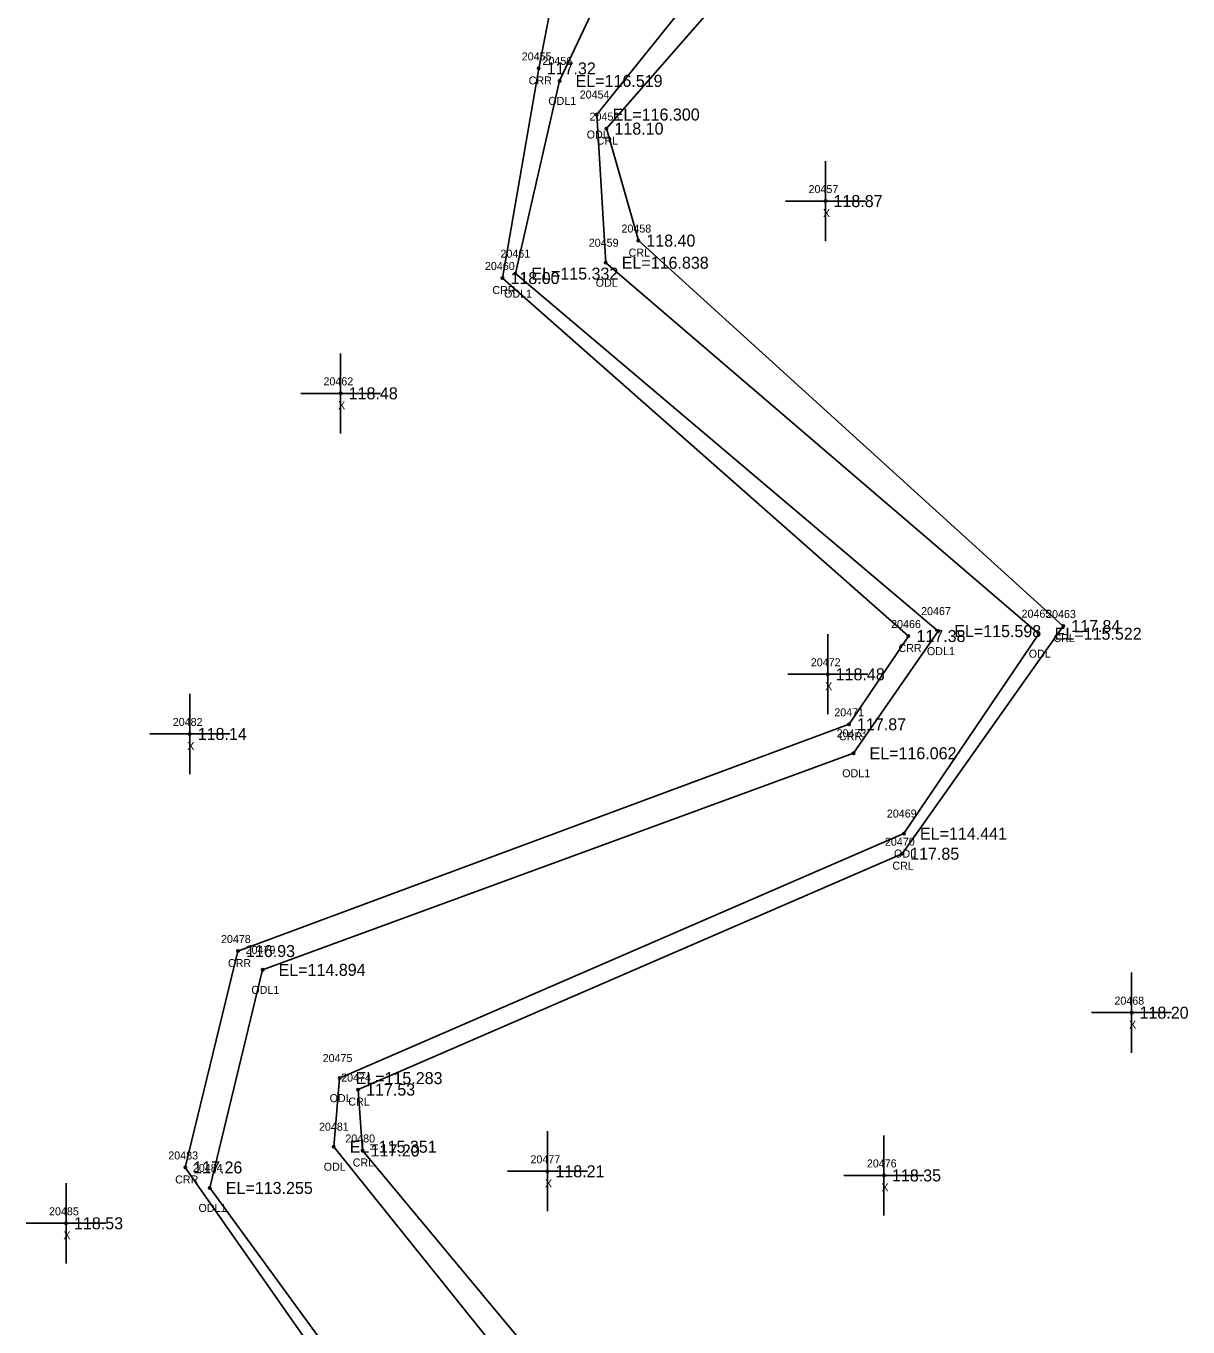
# Model space of a CAD drawing. Extents: x 2375812 to 2377225, y 1024470 to 1025135.
# Drawn here: x 2376487.2 to 2376632.4, y 1024633 to 1024795.6 of the extents above; entities that cross this region are included whole.
import ezdxf

# ---------------------------------------------------------------- set-up
doc = ezdxf.new("R2010")
doc.units = 0
for name, color, linetype in [('RD_EX_H2O', 7, 'Continuous'), ('RD_EX_H2O_txCode', 7, 'Continuous'), ('RD_EX_Misc', 7, 'Continuous'), ('RD_EX_Misc_txCode', 7, 'Continuous'), ('RD_EX_TX_H2O_ELEV', 7, 'Continuous'), ('RD_EX_TX_Misc_ELEV', 7, 'Continuous'), ('RD_SMD_Locator', 7, 'Continuous')]:
    doc.layers.add(name, color=color, linetype=linetype)

msp = doc.modelspace()

# ---------------------------------------------------------------- linework, layer by layer
at = {"layer": 'RD_EX_H2O'}
for points in [[(2376521.35, 1025122.45), (2376536.92, 1025091.14), (2376540.63, 1025083.08), (2376543.66, 1025055.12), (2376543.73, 1025030.97), (2376527.94, 1024982.48), (2376525.52, 1024962.71), (2376529, 1024940.86), (2376531.15, 1024912.48), (2376521.82, 1024868), (2376529.09, 1024848.8), (2376562.19, 1024842.5), (2376569.47, 1024830.15), (2376574.05, 1024803.85), (2376558.51, 1024784.52), (2376559.64, 1024766), (2376613.77, 1024719.65), (2376596.93, 1024694.68), (2376526.36, 1024664.12), (2376525.63, 1024655.55), (2376574.03, 1024595.3), (2376579.09, 1024545.56), (2376560.1, 1024512.81), (2376580.22, 1024476.29)], [(2376510.41, 1025118.87), (2376524.18, 1025090.35), (2376517.39, 1025079.83), (2376512.07, 1025056.47), (2376513.2, 1025032.16), (2376507.89, 1024984.65), (2376510.96, 1024957.77), (2376506.15, 1024940.79), (2376503.27, 1024912.21), (2376508.8, 1024872.61), (2376520.24, 1024833.34), (2376559.55, 1024828.46), (2376560.55, 1024802.93), (2376553.87, 1024788.72), (2376548.34, 1024764.64), (2376601.21, 1024719.97), (2376590.62, 1024704.71), (2376516.74, 1024677.65), (2376510.14, 1024650.4), (2376567.6, 1024571.64), (2376569.87, 1024553.24), (2376548.12, 1024513.5), (2376565.22, 1024475.98)], [(2376554.79, 1024808.22), (2376551.26, 1024790.28), (2376546.73, 1024764.09), (2376597.49, 1024719.36), (2376590.06, 1024708.33), (2376513.66, 1024680), (2376507.07, 1024652.96), (2376563.64, 1024572.19), (2376565.26, 1024557.08), (2376545.13, 1024513.67), (2376559.22, 1024475.85)], [(2376577.78, 1024803.44), (2376559.73, 1024782.76), (2376563.72, 1024768.77), (2376616.84, 1024720.6), (2376596.7, 1024692.16), (2376528.68, 1024662.69), (2376529.24, 1024655.08), (2376574.47, 1024600.74), (2376581.85, 1024543.26), (2376561.1, 1024512.75), (2376586.22, 1024476.41)]]:
    msp.add_lwpolyline(points, dxfattribs=at)
at = {"layer": 'RD_EX_Misc'}
for p, q in [((2376587.12, 1024768.7), (2376587.12, 1024778.7)), ((2376582.12, 1024773.7), (2376592.12, 1024773.7)), ((2376526.5, 1024744.68), (2376526.5, 1024754.68)), ((2376521.5, 1024749.68), (2376531.5, 1024749.68)), ((2376587.39, 1024709.58), (2376587.39, 1024719.58)), ((2376582.39, 1024714.58), (2376592.39, 1024714.58)), ((2376507.63, 1024702.12), (2376507.63, 1024712.12)), ((2376502.63, 1024707.12), (2376512.63, 1024707.12)), ((2376625.38, 1024667.3), (2376625.38, 1024677.3)), ((2376620.38, 1024672.3), (2376630.38, 1024672.3)), ((2376552.35, 1024647.48), (2376552.35, 1024657.48)), ((2376594.43, 1024646.96), (2376594.43, 1024656.96)), ((2376547.35, 1024652.48), (2376557.35, 1024652.48)), ((2376492.16, 1024640.98), (2376492.16, 1024650.98)), ((2376589.43, 1024651.96), (2376599.43, 1024651.96)), ((2376487.16, 1024645.98), (2376497.16, 1024645.98))]:
    msp.add_line(p, q, dxfattribs=at)
at = {"layer": 'RD_SMD_Locator'}
for centre in [(2376551.26, 1024790.28), (2376553.87, 1024788.72), (2376558.51, 1024784.52), (2376559.73, 1024782.76), (2376587.12, 1024773.7), (2376563.72, 1024768.77), (2376559.64, 1024766), (2376546.73, 1024764.09), (2376548.34, 1024764.64), (2376526.5, 1024749.68), (2376616.84, 1024720.6), (2376597.49, 1024719.36), (2376601.21, 1024719.97), (2376613.77, 1024719.65), (2376587.39, 1024714.58), (2376590.06, 1024708.33), (2376507.63, 1024707.12), (2376590.62, 1024704.71), (2376596.93, 1024694.68), (2376596.7, 1024692.16), (2376513.66, 1024680), (2376516.74, 1024677.65), (2376625.38, 1024672.3), (2376526.36, 1024664.12), (2376528.68, 1024662.69), (2376525.63, 1024655.55), (2376529.24, 1024655.08), (2376507.07, 1024652.96), (2376552.35, 1024652.48), (2376594.43, 1024651.96), (2376510.14, 1024650.4), (2376492.16, 1024645.98)]:
    msp.add_circle(centre, 0.15, dxfattribs=at)

# ---------------------------------------------------------------- texts
at = {"layer": 'RD_EX_H2O_txCode'}
for s, p in [('20455', (2376549.14, 1024791.28)), ('20456', (2376551.73, 1024790.72)), ('CRR', (2376550.01, 1024788.28)), ('20454', (2376556.39, 1024786.52)), ('ODL1', (2376552.46, 1024785.72)), ('20453', (2376557.62, 1024783.76)), ('ODL', (2376557.26, 1024781.52)), ('CRL', (2376558.51, 1024780.76)), ('20458', (2376561.61, 1024769.77)), ('20461', (2376546.48, 1024766.64)), ('20459', (2376557.52, 1024768)), ('CRL', (2376562.5, 1024766.77)), ('20460', (2376544.54, 1024765.09)), ('CRR', (2376545.47, 1024762.09)), ('ODL1', (2376546.93, 1024761.64)), ('ODL', (2376558.39, 1024763)), ('20467', (2376599.07, 1024721.97)), ('20465', (2376611.63, 1024721.65)), ('20463', (2376614.7, 1024721.6)), ('20466', (2376595.32, 1024720.36)), ('CRL', (2376615.62, 1024718.6)), ('CRR', (2376596.24, 1024717.36)), ('ODL1', (2376599.8, 1024716.97)), ('ODL', (2376612.53, 1024716.65)), ('20471', (2376588.22, 1024709.33)), ('20473', (2376588.51, 1024706.71)), ('CRR', (2376588.8, 1024706.33)), ('ODL1', (2376589.21, 1024701.71)), ('20469', (2376594.79, 1024696.68)), ('20470', (2376594.55, 1024693.16)), ('ODL', (2376595.69, 1024691.68)), ('CRL', (2376595.48, 1024690.16)), ('20478', (2376511.54, 1024681)), ('20479', (2376514.62, 1024679.65)), ('CRR', (2376512.41, 1024678)), ('ODL1', (2376515.33, 1024674.65)), ('20475', (2376524.25, 1024666.12)), ('20474', (2376526.56, 1024663.69)), ('ODL', (2376525.12, 1024661.12)), ('CRL', (2376527.45, 1024660.69)), ('20481', (2376523.79, 1024657.55)), ('20480', (2376527.08, 1024656.08)), ('20483', (2376504.95, 1024653.96)), ('CRL', (2376528.01, 1024653.08)), ('20484', (2376508.02, 1024652.4)), ('ODL', (2376524.38, 1024652.55)), ('CRR', (2376505.81, 1024650.96)), ('ODL1', (2376508.73, 1024647.4))]:
    msp.add_text(s, height=1, dxfattribs=at).set_placement(p)
at = {"layer": 'RD_EX_Misc_txCode'}
for s, p in [('20457', (2376585, 1024774.7)), ('X', (2376586.8, 1024771.7)), ('20462', (2376524.35, 1024750.68)), ('X', (2376526.18, 1024747.68)), ('20472', (2376585.28, 1024715.58)), ('X', (2376587.08, 1024712.58)), ('20482', (2376505.51, 1024708.12)), ('X', (2376507.32, 1024705.12)), ('20468', (2376623.24, 1024673.3)), ('X', (2376625.07, 1024670.3)), ('20477', (2376550.23, 1024653.48)), ('20476', (2376592.29, 1024652.96)), ('X', (2376552.04, 1024650.48)), ('X', (2376594.11, 1024649.96)), ('20485', (2376490.04, 1024646.98)), ('X', (2376491.84, 1024643.98))]:
    msp.add_text(s, height=1, dxfattribs=at).set_placement(p)
at = {"layer": 'RD_EX_TX_H2O_ELEV'}
for s, p in [('117.32', (2376552.26, 1024789.53)), ('EL=116.519', (2376555.87, 1024787.97)), ('EL=116.300', (2376560.51, 1024783.77)), ('118.10', (2376560.73, 1024782.01)), ('118.40', (2376564.72, 1024768.02)), ('EL=116.838', (2376561.64, 1024765.25)), ('118.00', (2376547.73, 1024763.34)), ('EL=115.332', (2376550.34, 1024763.89)), ('EL=115.598', (2376603.21, 1024719.22)), ('EL=115.522', (2376615.77, 1024718.9)), ('117.84', (2376617.84, 1024719.85)), ('117.38', (2376598.49, 1024718.61)), ('117.87', (2376591.06, 1024707.58)), ('EL=116.062', (2376592.62, 1024703.96)), ('EL=114.441', (2376598.93, 1024693.93)), ('117.85', (2376597.7, 1024691.41)), ('116.93', (2376514.66, 1024679.25)), ('EL=114.894', (2376518.74, 1024676.9)), ('EL=115.283', (2376528.36, 1024663.37)), ('117.53', (2376529.68, 1024661.94)), ('EL=115.351', (2376527.63, 1024654.8)), ('117.20', (2376530.24, 1024654.33)), ('117.26', (2376508.07, 1024652.21)), ('EL=113.255', (2376512.14, 1024649.65))]:
    msp.add_text(s, height=1.5, dxfattribs=at).set_placement(p)
at = {"layer": 'RD_EX_TX_Misc_ELEV'}
for s, p in [('118.87', (2376588.12, 1024772.95)), ('118.48', (2376527.5, 1024748.93)), ('118.48', (2376588.39, 1024713.83)), ('118.14', (2376508.63, 1024706.37)), ('118.20', (2376626.38, 1024671.55)), ('118.21', (2376553.35, 1024651.73)), ('118.35', (2376595.43, 1024651.21)), ('118.53', (2376493.16, 1024645.23))]:
    msp.add_text(s, height=1.5, dxfattribs=at).set_placement(p)

doc.saveas('drawing.dxf')
